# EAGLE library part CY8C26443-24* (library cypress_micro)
The CY8C25xxx/26xxx family of Programmable System-on-Chip (PSoC) microcontrollers offers a fast core, Flash program memory and SRAM data memory with configurable analog and digital peripheral blocks in a range of convinient pinouts and memory size on one single chip.
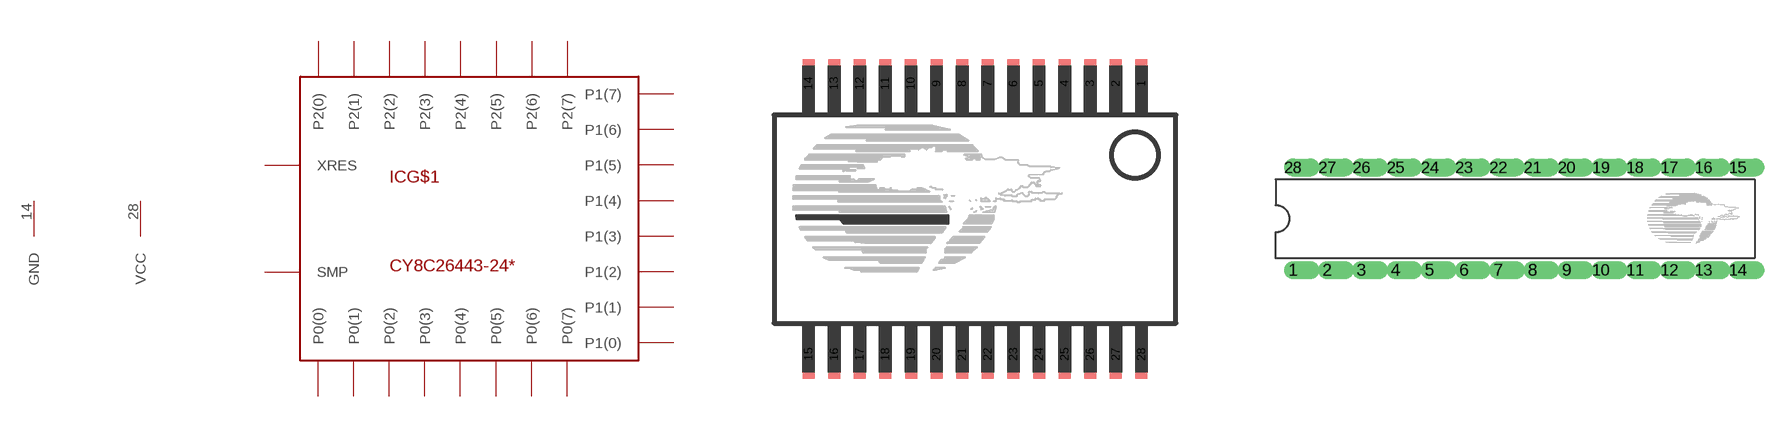
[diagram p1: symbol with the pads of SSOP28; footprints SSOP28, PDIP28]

Designator prefix IC; gates G$1=CY8C26443 G$2=GND G$3=VCC

## CY8C26443-24PVI  [SSOP28]
1  G$1:P0(7)
2  G$1:P0(5)
3  G$1:P0(3)
4  G$1:P0(1)
5  G$1:P2(7)
6  G$1:P2(5)
7  G$1:P2(3)
8  G$1:P2(1)
9  G$1:SMP  out
10  G$1:P1(7)
11  G$1:P1(5)
12  G$1:P1(3)
13  G$1:P1(1)
14  G$2:GND  pwr
15  G$1:P1(0)
16  G$1:P1(2)
17  G$1:P1(4)
18  G$1:P1(6)
19  G$1:XRES  in
20  G$1:P2(0)
21  G$1:P2(2)
22  G$1:P2(4)
23  G$1:P2(6)
24  G$1:P0(0)
25  G$1:P0(2)
26  G$1:P0(4)
27  G$1:P0(6)
28  G$3:VCC  pwr

## CY8C26443-24PI  [PDIP28]
Pads as for SSOP28

## CY8C26443-24SI  [SOIC28]
Pads as for SSOP28

## Footprint SSOP28 (pad centres in mm)
Shrunk Small Outline Package with 28 Pins
smd 0.305 x 1.245: 1 4.224,3.441; 2 3.574,3.441; 3 2.924,3.441; 4 2.274,3.441; 5 1.624,3.441; 6 0.974,3.441; 7 0.325,3.44; 8 -0.326,3.441; 9 -0.976,3.441; 10 -1.626,3.441; 11 -2.276,3.441; 12 -2.926,3.441; 13 -3.576,3.441; 14 -4.226,3.441; 15 -4.224,-3.441; 16 -3.574,-3.441; 17 -2.924,-3.441; 18 -2.274,-3.441; 19 -1.624,-3.441; 20 -0.974,-3.441; 21 -0.324,-3.441; 22 0.326,-3.441; 23 0.976,-3.441; 24 1.626,-3.441; 25 2.276,-3.441; 26 2.926,-3.441; 27 3.576,-3.441; 28 4.226,-3.441

## Footprint PDIP28 (pad centres in mm)
Plastic Dual Inline Package with 28 pins
drill 0.813 offset: 1 -16.51,-3.81; 2 -13.97,-3.81; 3 -11.43,-3.81; 4 -8.89,-3.81; 5 -6.35,-3.81; 6 -3.81,-3.81; 7 -1.27,-3.81; 8 1.27,-3.81; 9 3.81,-3.81; 10 6.35,-3.81; 11 8.89,-3.81; 12 11.43,-3.81; 13 13.97,-3.81; 14 16.51,-3.81; 15 16.51,3.81; 16 13.97,3.81; 17 11.43,3.81; 18 8.89,3.81; 19 6.35,3.81; 20 3.81,3.81; 21 1.27,3.81; 22 -1.27,3.81; 23 -3.81,3.81; 24 -6.35,3.81; 25 -8.89,3.81; 26 -11.43,3.81; 27 -13.97,3.81; 28 -16.51,3.81

## Footprint SOIC28 (pad centres in mm)
SOIC with 20 pins
smd 0.6 x 2.2: 1 8.89,4.548; 2 7.62,4.548; 3 6.35,4.548; 4 5.08,4.548; 5 3.81,4.548; 6 2.54,4.548; 7 1.27,4.548; 8 0,4.548; 9 -1.27,4.548; 10 -2.54,4.548; 11 -3.81,4.548; 12 -5.08,4.548; 13 -6.35,4.548; 14 -7.62,4.548; 15 -7.62,-4.548; 16 -6.35,-4.548; 17 -5.08,-4.548; 18 -3.81,-4.548; 19 -2.54,-4.548; 20 -1.27,-4.548; 21 0,-4.548; 22 1.27,-4.548; 23 2.54,-4.548; 24 3.81,-4.548; 25 5.08,-4.548; 26 6.35,-4.548; 27 7.62,-4.548; 28 8.89,-4.548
